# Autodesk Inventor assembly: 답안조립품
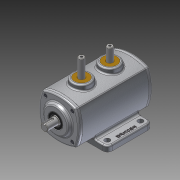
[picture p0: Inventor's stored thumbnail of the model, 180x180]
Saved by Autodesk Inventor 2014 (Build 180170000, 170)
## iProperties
Created: 2015-07
Part Number: 답안조립품
Document SubType Name: Assembly
Designer: Administrator
Mass: 2515.11 g
Surface Area: 1894.5 cm^2
Volume: 719.239 cm^3
Density: 3.4969 g/cm^3
Author: Administrator
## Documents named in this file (12)
- C:\Users\Administrator\Desktop\350727V1001\답안조립품.iam
- C:\Users\Administrator\Desktop\350727V1001\본체.ipt
- C:\Users\Administrator\Desktop\350727V1001\앞커버.ipt
- C:\Users\Administrator\Desktop\350727V1001\뒷커버.ipt
- C:\Users\Administrator\Desktop\350727V1001\베어링 6203.ipt
- C:\Users\Administrator\Desktop\350727V1001\오일실.ipt
- C:\Users\Administrator\Desktop\350727V1001\M4-소켓머리.ipt
- C:\Users\Administrator\Desktop\350727V1001\부시.ipt
- C:\Users\Administrator\Desktop\350727V1001\축.ipt
- C:\Users\Administrator\Desktop\350727V1001\스프링_01 [가변부품].ipt
- C:\Users\Administrator\Desktop\350727V1001\슬라이더.ipt
- C:\Users\Administrator\Desktop\350727V1001\스프링_02 [가변부품].ipt
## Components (11 placed, 3 different names)
1. 7-베어링 6203:1 — 각도:1
2. 7-베어링 6203:2 — 각도:2
3. 8-오일실:1
4. 9-M4-소켓머리:1
5. 9-M4-소켓머리:2
6. 9-M4-소켓머리:3
7. 9-M4-소켓머리:4
8. 9-M4-소켓머리:5
9. 9-M4-소켓머리:6
10. 9-M4-소켓머리:7
11. 9-M4-소켓머리:8
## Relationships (2: Angle 2)
- 각도:1 [Angle]: 7-베어링 6203:1
- 각도:2 [Angle]: 7-베어링 6203:2
